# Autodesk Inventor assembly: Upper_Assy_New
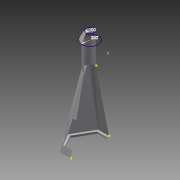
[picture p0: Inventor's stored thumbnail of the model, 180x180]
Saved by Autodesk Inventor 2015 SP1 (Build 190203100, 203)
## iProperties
Created: 2013-06
Part Number: Upper_Assy_New
Document SubType Name: Assembly
Designer: BarryWSUK
Author: BarryWSUK
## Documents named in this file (6)
- \\psf\Home\Documents\Inventor\Sau Paulo Chimnea\Upper_Assy_New.iam
- \\psf\Home\Documents\Inventor\Sau Paulo Chimnea\Flue.ipt
- \\psf\Home\Documents\Inventor\Sau Paulo Chimnea\Lid Straps.ipt
- \\psf\Home\Documents\Inventor\Sau Paulo Chimnea\Lid.ipt
- \\psf\Home\Documents\Inventor\Sau Paulo Chimnea\IFI 520 - 43 x 3.3(3).ipt
- \\psf\Home\Documents\Inventor\Sau Paulo Chimnea\Hex to Round New.ipt
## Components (15 placed, 5 different names)
1. Hex to Round New:1 — Mate:1, Mate:2, Mate:6
2. Flue:1 — Mate:1, Mate:2, Tangent:1, Angle:1, Mate:4, Flush:2, Mate:5, Mate:6, Mate:7, Tangent:2
3. Lid:1 — Mate:4, Flush:2, Mate:5, Flush:3
4. Lid Straps:2 — Tangent:1, Angle:1, Mate:7
5. Lid Straps:3 — Mate:8, Insert:1
6. Lid Straps:4 — Flush:3
7. IFI 520 - 43 x 3.3(3):1 — Insert:1
8. IFI 520 - 43 x 3.3(3):5
9. IFI 520 - 43 x 3.3(3):8
10. IFI 520 - 43 x 3.3(3):3 — Tangent:2, Mate:8
11. IFI 520 - 43 x 3.3(3):4
12. IFI 520 - 43 x 3.3(3):6
13. IFI 520 - 43 x 3.3(3):7
14. IFI 520 - 43 x 3.3(3):9
15. IFI 520 - 43 x 3.3(3):10
## Component patterns: Component Pattern 3:2 (2 elements), Component Pattern 3:3 (2 elements)
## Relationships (13: Mate 7, Tangent 2, Flush 2, Angle 1, Insert 1)
- Mate:1: Hex to Round New:1 ↔ Flue:1
- Mate:2: Hex to Round New:1 ↔ Flue:1
- Tangent:1: Flue:1 ↔ Lid Straps:2
- Angle:1: Flue:1 ↔ Lid Straps:2
- Mate:4: Flue:1 ↔ Lid:1
- Flush:2: Flue:1 ↔ Lid:1
- Mate:5: Flue:1 ↔ Lid:1
- Mate:6: Hex to Round New:1 ↔ Flue:1
- Mate:7: Flue:1 ↔ Lid Straps:2
- Tangent:2: Flue:1 ↔ IFI 520 - 43 x 3.3(3):3
- Mate:8: Lid Straps:3 ↔ IFI 520 - 43 x 3.3(3):3
- Flush:3: Lid:1 ↔ Lid Straps:4
- Insert:1: Lid Straps:3 ↔ IFI 520 - 43 x 3.3(3):1
